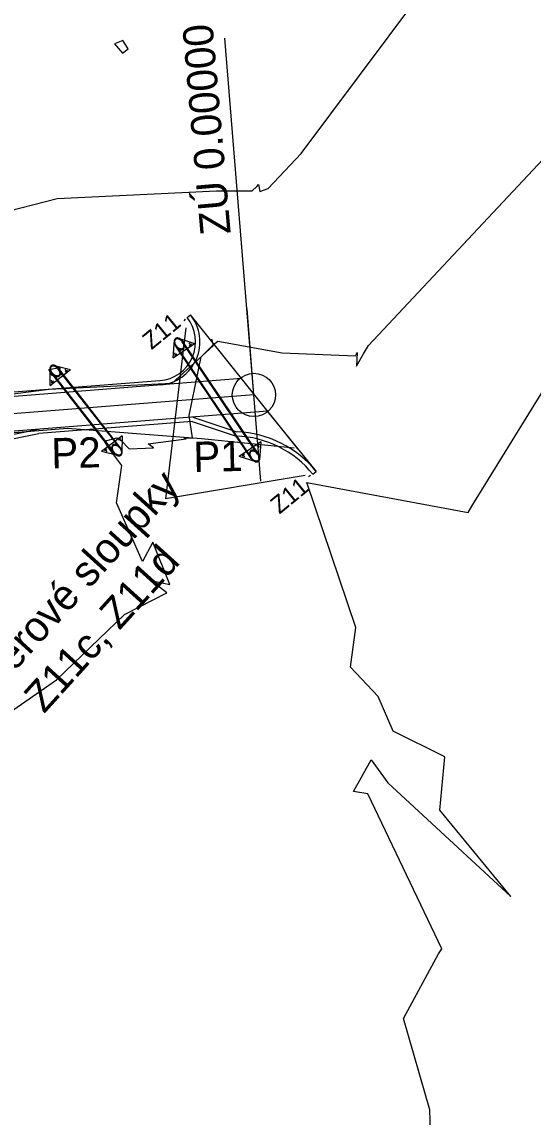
# Model space of a CAD drawing. Extents: x -549394 to -546608, y -1037055 to -1033629.
# Drawn here: x -547531.9 to -547472.7, y -1035190.9 to -1035064.3 of the extents above; entities that cross this region are included whole.
import ezdxf

# ---------------------------------------------------------------- set-up
doc = ezdxf.new("R2010")
doc.units = 0
for name, color, linetype in [('hlavni_vrst', 7, 'Continuous'), ('hrana_L', 7, 'Continuous'), ('norm_vrst', 7, 'Continuous'), ('POLYGONY_SITUACE_PO', 7, 'Continuous'), ('x_navrh_C1', 7, 'Continuous'), ('x_osa_C1', 7, 'Continuous'), ('x_popis_C1', 7, 'Continuous'), ('x_popis_oblouky_C1', 7, 'Continuous'), ('x_popis_pricne_rezy_C1', 7, 'Continuous'), ('x_propustek', 7, 'Continuous'), ('x_SDZ_C1', 7, 'Continuous')]:
    doc.layers.add(name, color=color, linetype=linetype)

msp = doc.modelspace()

# ---------------------------------------------------------------- linework, layer by layer
at = {"layer": 'hlavni_vrst'}
for p, q in [((-547479.83, -1035120.29), (-547467.32, -1035100.01)), ((-547498.94, -1035117.55), (-547498.94, -1035117.55)), ((-547498.94, -1035117.55), (-547498.94, -1035117.55)), ((-547498.94, -1035117.55), (-547498.94, -1035117.55)), ((-547498.94, -1035117.55), (-547480.25, -1035121.02)), ((-547498.94, -1035117.55), (-547498.94, -1035117.55)), ((-547493.26, -1035134.32), (-547498.94, -1035117.55)), ((-547498.94, -1035117.55), (-547498.94, -1035117.55)), ((-547498.94, -1035117.55), (-547498.94, -1035117.55)), ((-547498.94, -1035117.55), (-547498.94, -1035117.55)), ((-547480.25, -1035121.02), (-547479.83, -1035120.29)), ((-547493.87, -1035138.92), (-547493.26, -1035134.32)), ((-547490.66, -1035142.33), (-547493.87, -1035138.92)), ((-547488.93, -1035146.33), (-547490.66, -1035142.33)), ((-547482.97, -1035149.28), (-547488.93, -1035146.33)), ((-547493.51, -1035153.28), (-547491.47, -1035149.64)), ((-547491.47, -1035149.64), (-547489.56, -1035152.3)), ((-547483.54, -1035155.44), (-547482.97, -1035149.28)), ((-547489.56, -1035152.3), (-547475.31, -1035165.43)), ((-547491.88, -1035153.58), (-547493.51, -1035153.28)), ((-547483.29, -1035171.5), (-547491.88, -1035153.58)), ((-547475.31, -1035165.43), (-547483.54, -1035155.44)), ((-547483.7, -1035172.06), (-547483.29, -1035171.5)), ((-547487.72, -1035179.56), (-547483.7, -1035172.06)), ((-547484.7, -1035190.12), (-547487.72, -1035179.56)), ((-547483.99, -1035210.2), (-547484.7, -1035190.12))]:
    msp.add_line(p, q, dxfattribs=at)
at = {"layer": 'hrana_L'}
for p, q in [((-547509.73, -1035101.72), (-547514.54, -1035106.1)), ((-547509.73, -1035101.72), (-547509.94, -1035101)), ((-547528.76, -1035106.82), (-547550.14, -1035109.56)), ((-547514.54, -1035106.1), (-547528.76, -1035106.82)), ((-547540.44, -1035112.37), (-547526.63, -1035111.28)), ((-547526.63, -1035111.28), (-547511.12, -1035112.47)), ((-547511.12, -1035112.47), (-547500.41, -1035113.54))]:
    msp.add_line(p, q, dxfattribs=at)
at = {"layer": 'norm_vrst'}
for p, q in [((-547499.6, -1035079.52), (-547480.94, -1035054.58)), ((-547520.21, -1035066.44), (-547521.2, -1035066.83)), ((-547519.62, -1035067.42), (-547520.21, -1035066.44)), ((-547521.2, -1035066.83), (-547520.26, -1035067.93)), ((-547520.26, -1035067.93), (-547519.62, -1035067.42)), ((-547491.77, -1035101.71), (-547459.89, -1035067.67)), ((-547503.4, -1035083.58), (-547499.6, -1035079.52)), ((-547527.84, -1035084.74), (-547509.37, -1035083.84)), ((-547509.37, -1035083.84), (-547505.24, -1035083.85)), ((-547505.24, -1035083.85), (-547504.71, -1035083.33)), ((-547504.71, -1035083.33), (-547504.53, -1035083.09)), ((-547504.53, -1035083.09), (-547504.35, -1035083.91)), ((-547504.35, -1035083.91), (-547503.4, -1035083.58)), ((-547535.88, -1035086.78), (-547527.84, -1035084.74)), ((-547511.17, -1035103.03), (-547509.75, -1035101.64)), ((-547509.75, -1035101.64), (-547509.24, -1035101.21)), ((-547509.24, -1035101.21), (-547501.78, -1035102.57)), ((-547492.36, -1035102.68), (-547491.77, -1035101.71)), ((-547512.55, -1035109.82), (-547511.17, -1035103.03)), ((-547501.78, -1035102.57), (-547493.31, -1035102.92)), ((-547493.31, -1035102.92), (-547493.12, -1035102.53)), ((-547493.12, -1035102.53), (-547493.18, -1035104.1)), ((-547493.18, -1035104.1), (-547492.36, -1035102.68)), ((-547528.79, -1035104.51), (-547527.52, -1035104.28)), ((-547527.52, -1035104.28), (-547527.55, -1035104.73)), ((-547528.43, -1035105.18), (-547528.79, -1035104.51)), ((-547528, -1035105.18), (-547528.43, -1035105.18)), ((-547527.97, -1035105.44), (-547528, -1035105.18)), ((-547527.34, -1035105.07), (-547527.97, -1035105.44)), ((-547527.55, -1035104.73), (-547527.34, -1035105.07)), ((-547512.17, -1035112.39), (-547512.55, -1035109.82)), ((-547522.36, -1035112.78), (-547520.92, -1035112.39)), ((-547521.86, -1035113.6), (-547522.36, -1035112.78)), ((-547520.92, -1035112.39), (-547520.45, -1035112.67)), ((-547520.45, -1035112.67), (-547519.48, -1035113.67)), ((-547517.3, -1035113.1), (-547512.88, -1035112.5)), ((-547516.67, -1035113.57), (-547517.3, -1035113.1)), ((-547513.13, -1035112.4), (-547512.17, -1035112.39)), ((-547512.88, -1035112.5), (-547513.13, -1035112.4)), ((-547520.33, -1035115.59), (-547521.86, -1035113.6)), ((-547519.48, -1035113.67), (-547516.67, -1035113.57)), ((-547520.94, -1035119.91), (-547520.33, -1035115.59)), ((-547517.94, -1035126.69), (-547520.94, -1035119.91)), ((-547516.76, -1035124.47), (-547517.94, -1035126.69)), ((-547514.77, -1035129.37), (-547516.76, -1035124.47)), ((-547515.15, -1035130.32), (-547516.97, -1035128.88)), ((-547516.97, -1035128.88), (-547514.77, -1035129.37)), ((-547520.05, -1035132.83), (-547515.15, -1035130.32)), ((-547527.89, -1035140.38), (-547520.05, -1035132.83)), ((-547540.33, -1035148.97), (-547527.89, -1035140.38))]:
    msp.add_line(p, q, dxfattribs=at)
at = {"layer": 'POLYGONY_SITUACE_PO'}
msp.add_circle((-547505.05, -1035107.44), 2.5, dxfattribs=at)
at = {"layer": 'x_navrh_C1'}
for p, q in [((-547512.79, -1035098.49), (-547512.4, -1035098.17)), ((-547499.96, -1035113.69), (-547512.4, -1035098.17)), ((-547506.49, -1035105.54), (-547540.28, -1035108.21)), ((-547503.46, -1035109.32), (-547539.97, -1035112.19)), ((-547503.51, -1035109.32), (-547497.84, -1035116.3)), ((-547512.19, -1035110.51), (-547529.93, -1035111.9)), ((-547512.19, -1035110.51), (-547507.1, -1035112.19)), ((-547512.13, -1035110), (-547507.01, -1035111.69)), ((-547539.87, -1035113.39), (-547530, -1035111.41)), ((-547539.81, -1035113.89), (-547529.93, -1035111.9)), ((-547498.22, -1035116.61), (-547497.84, -1035116.3))]:
    msp.add_line(p, q, dxfattribs=at)
msp.add_lwpolyline([(-547515.94, -1035105.79), (-547540.32, -1035107.71)], dxfattribs=at)
for centre, radius, start, end in [((-547516.3, -1035101.3), 4.5, 274.5085, 38.7215), ((-547516.3, -1035101.3), 5, 274.5085, 38.7215), ((-547507.53, -1035124.18), 12.5, 39.1118, 87.5903), ((-547507.53, -1035124.18), 12, 39.1118, 87.9203)]:
    msp.add_arc(centre, radius, start, end, dxfattribs=at)
at = {"layer": 'x_osa_C1'}
msp.add_lwpolyline([(-547505.05, -1035107.44), (-547549.17, -1035110.91)], dxfattribs=at)
at = {"layer": 'x_popis_oblouky_C1'}
msp.add_lwpolyline([(-547505.05, -1035107.44), (-547508.42, -1035066.2)], dxfattribs=at)
at = {"layer": 'x_popis_pricne_rezy_C1'}
msp.add_lwpolyline([(-547504.26, -1035117.4), (-547505.05, -1035107.44), (-547505.84, -1035097.47)], dxfattribs=at)
at = {"layer": 'x_propustek'}
for p, q in [((-547514.41, -1035103.15), (-547514.25, -1035101.09)), ((-547514.41, -1035103.15), (-547511.92, -1035101.48)), ((-547513.89, -1035100.85), (-547514.25, -1035101.09)), ((-547505.38, -1035114.77), (-547514.1, -1035101.8)), ((-547505.32, -1035114.73), (-547514.03, -1035101.76)), ((-547513.89, -1035100.85), (-547511.92, -1035101.48)), ((-547504.63, -1035114.27), (-547513.35, -1035101.3)), ((-547504.57, -1035114.22), (-547513.29, -1035101.26)), ((-547512.31, -1035101.74), (-547512.53, -1035101.41)), ((-547512.39, -1035101.8), (-547512.5, -1035101.63)), ((-547512.23, -1035101.69), (-547512.34, -1035101.52)), ((-547514.02, -1035102.89), (-547514.24, -1035102.56)), ((-547514.1, -1035102.94), (-547514.21, -1035102.78)), ((-547513.93, -1035102.83), (-547514.04, -1035102.67)), ((-547528.65, -1035106.33), (-547528.64, -1035104.26)), ((-547528.65, -1035106.33), (-547526.29, -1035104.49)), ((-547528.3, -1035104), (-547528.64, -1035104.26)), ((-547528.3, -1035104), (-547526.29, -1035104.49)), ((-547520.59, -1035113.56), (-547527.73, -1035104.41)), ((-547520.53, -1035113.52), (-547527.67, -1035104.36)), ((-547526.66, -1035104.78), (-547526.91, -1035104.46)), ((-547528.28, -1035106.04), (-547528.53, -1035105.72)), ((-547521.3, -1035114.12), (-547528.44, -1035104.96)), ((-547521.24, -1035114.07), (-547528.38, -1035104.91)), ((-547526.74, -1035104.84), (-547526.86, -1035104.68)), ((-547526.58, -1035104.71), (-547526.7, -1035104.56)), ((-547528.36, -1035106.1), (-547528.48, -1035105.94)), ((-547528.2, -1035105.98), (-547528.33, -1035105.82)), ((-547520.31, -1035112.15), (-547522.68, -1035113.99)), ((-547520.76, -1035112.5), (-547520.64, -1035112.66)), ((-547520.68, -1035112.44), (-547520.44, -1035112.75)), ((-547520.61, -1035112.38), (-547520.48, -1035112.53)), ((-547520.31, -1035112.15), (-547520.33, -1035114.22)), ((-547504.26, -1035112.87), (-547506.75, -1035114.55)), ((-547504.74, -1035113.19), (-547504.63, -1035113.36)), ((-547504.65, -1035113.14), (-547504.43, -1035113.47)), ((-547504.57, -1035113.08), (-547504.46, -1035113.25)), ((-547504.26, -1035112.87), (-547504.42, -1035114.94)), ((-547520.66, -1035114.48), (-547522.68, -1035113.99)), ((-547522.38, -1035113.76), (-547522.26, -1035113.92)), ((-547522.31, -1035113.7), (-547522.06, -1035114.02)), ((-547522.23, -1035113.64), (-547522.1, -1035113.8)), ((-547520.66, -1035114.48), (-547520.33, -1035114.22)), ((-547504.78, -1035115.18), (-547506.75, -1035114.55)), ((-547506.44, -1035114.34), (-547506.33, -1035114.51)), ((-547506.36, -1035114.28), (-547506.14, -1035114.62)), ((-547506.28, -1035114.23), (-547506.17, -1035114.39)), ((-547504.78, -1035115.18), (-547504.42, -1035114.94))]:
    msp.add_line(p, q, dxfattribs=at)
for points in [[(-547514.11, -1035100.91), (-547514.12, -1035100.91), (-547514.14, -1035100.92), (-547514.16, -1035100.95), (-547514.17, -1035100.96), (-547514.2, -1035100.99), (-547514.22, -1035101.02), (-547514.26, -1035101.12), (-547514.28, -1035101.19), (-547514.27, -1035101.36), (-547514.26, -1035101.45), (-547514.2, -1035101.63), (-547514.15, -1035101.72), (-547514.04, -1035101.89), (-547513.97, -1035101.96), (-547513.83, -1035102.08), (-547513.75, -1035102.13), (-547513.6, -1035102.2), (-547513.52, -1035102.21), (-547513.44, -1035102.21), (-547513.42, -1035102.21), (-547513.39, -1035102.2), (-547513.37, -1035102.2), (-547513.33, -1035102.18), (-547513.3, -1035102.17), (-547513.27, -1035102.15)], [(-547514.07, -1035100.97), (-547514.09, -1035100.98), (-547514.11, -1035101), (-547514.14, -1035101.04), (-547514.15, -1035101.06), (-547514.18, -1035101.11), (-547514.18, -1035101.14), (-547514.2, -1035101.2), (-547514.2, -1035101.24), (-547514.2, -1035101.31), (-547514.2, -1035101.35), (-547514.18, -1035101.43), (-547514.17, -1035101.47), (-547514.13, -1035101.6), (-547514.09, -1035101.68), (-547513.98, -1035101.84), (-547513.92, -1035101.91), (-547513.82, -1035101.99), (-547513.79, -1035102.02), (-547513.72, -1035102.06), (-547513.68, -1035102.08), (-547513.61, -1035102.11), (-547513.58, -1035102.12), (-547513.52, -1035102.13), (-547513.49, -1035102.14), (-547513.43, -1035102.13), (-547513.4, -1035102.13), (-547513.36, -1035102.12), (-547513.33, -1035102.1), (-547513.29, -1035102.08), (-547513.28, -1035102.06), (-547513.24, -1035102.02), (-547513.23, -1035102), (-547513.21, -1035101.95), (-547513.2, -1035101.92), (-547513.19, -1035101.86), (-547513.18, -1035101.82), (-547513.18, -1035101.75), (-547513.19, -1035101.71), (-547513.2, -1035101.63), (-547513.21, -1035101.58), (-547513.25, -1035101.46), (-547513.3, -1035101.38), (-547513.4, -1035101.22), (-547513.46, -1035101.15), (-547513.56, -1035101.07), (-547513.6, -1035101.04), (-547513.67, -1035101), (-547513.7, -1035100.98), (-547513.77, -1035100.95), (-547513.8, -1035100.94), (-547513.87, -1035100.93), (-547513.9, -1035100.92), (-547513.95, -1035100.92), (-547513.98, -1035100.93), (-547514.03, -1035100.94), (-547514.05, -1035100.95), (-547514.07, -1035100.97)], [(-547513.27, -1035102.15), (-547513.26, -1035102.14), (-547513.25, -1035102.14), (-547513.22, -1035102.11), (-547513.21, -1035102.1), (-547513.18, -1035102.07), (-547513.16, -1035102.04), (-547513.12, -1035101.94), (-547513.11, -1035101.87), (-547513.11, -1035101.7), (-547513.13, -1035101.61), (-547513.19, -1035101.43), (-547513.23, -1035101.34), (-547513.34, -1035101.17), (-547513.41, -1035101.1), (-547513.55, -1035100.98), (-547513.63, -1035100.93), (-547513.78, -1035100.86), (-547513.86, -1035100.85), (-547513.95, -1035100.85), (-547513.96, -1035100.85), (-547513.99, -1035100.86), (-547514.01, -1035100.86), (-547514.06, -1035100.87), (-547514.09, -1035100.89), (-547514.11, -1035100.91)], [(-547528.52, -1035104.07), (-547528.53, -1035104.08), (-547528.54, -1035104.09), (-547528.56, -1035104.11), (-547528.57, -1035104.12), (-547528.6, -1035104.16), (-547528.62, -1035104.19), (-547528.65, -1035104.29), (-547528.66, -1035104.36), (-547528.65, -1035104.53), (-547528.63, -1035104.62), (-547528.55, -1035104.8), (-547528.5, -1035104.88), (-547528.38, -1035105.04), (-547528.31, -1035105.11), (-547528.16, -1035105.22), (-547528.08, -1035105.27), (-547527.92, -1035105.32), (-547527.84, -1035105.33), (-547527.75, -1035105.32), (-547527.74, -1035105.32), (-547527.7, -1035105.31), (-547527.69, -1035105.31), (-547527.64, -1035105.29), (-547527.62, -1035105.27), (-547527.59, -1035105.25)], [(-547528.47, -1035104.13), (-547528.49, -1035104.14), (-547528.51, -1035104.16), (-547528.54, -1035104.2), (-547528.55, -1035104.22), (-547528.57, -1035104.28), (-547528.57, -1035104.31), (-547528.58, -1035104.37), (-547528.58, -1035104.41), (-547528.58, -1035104.48), (-547528.57, -1035104.52), (-547528.55, -1035104.6), (-547528.54, -1035104.64), (-547528.49, -1035104.76), (-547528.44, -1035104.84), (-547528.32, -1035104.99), (-547528.26, -1035105.05), (-547528.15, -1035105.13), (-547528.12, -1035105.16), (-547528.04, -1035105.19), (-547528.01, -1035105.21), (-547527.94, -1035105.23), (-547527.9, -1035105.24), (-547527.84, -1035105.25), (-547527.81, -1035105.25), (-547527.75, -1035105.24), (-547527.72, -1035105.24), (-547527.68, -1035105.22), (-547527.66, -1035105.21), (-547527.62, -1035105.18), (-547527.6, -1035105.16), (-547527.57, -1035105.12), (-547527.56, -1035105.1), (-547527.54, -1035105.04), (-547527.54, -1035105.02), (-547527.53, -1035104.95), (-547527.53, -1035104.92), (-547527.53, -1035104.84), (-547527.54, -1035104.8), (-547527.56, -1035104.72), (-547527.57, -1035104.68), (-547527.62, -1035104.56), (-547527.67, -1035104.48), (-547527.79, -1035104.33), (-547527.85, -1035104.27), (-547527.96, -1035104.19), (-547527.99, -1035104.17), (-547528.07, -1035104.13), (-547528.1, -1035104.11), (-547528.17, -1035104.09), (-547528.21, -1035104.08), (-547528.27, -1035104.07), (-547528.3, -1035104.07), (-547528.36, -1035104.08), (-547528.38, -1035104.08), (-547528.43, -1035104.1), (-547528.45, -1035104.11), (-547528.47, -1035104.13)], [(-547527.59, -1035105.25), (-547527.58, -1035105.24), (-547527.57, -1035105.23), (-547527.55, -1035105.21), (-547527.54, -1035105.2), (-547527.51, -1035105.16), (-547527.49, -1035105.13), (-547527.46, -1035105.03), (-547527.45, -1035104.96), (-547527.46, -1035104.79), (-547527.48, -1035104.7), (-547527.56, -1035104.53), (-547527.61, -1035104.44), (-547527.73, -1035104.28), (-547527.8, -1035104.21), (-547527.95, -1035104.1), (-547528.03, -1035104.05), (-547528.19, -1035104), (-547528.27, -1035103.99), (-547528.36, -1035104), (-547528.37, -1035104), (-547528.4, -1035104.01), (-547528.42, -1035104.02), (-547528.47, -1035104.03), (-547528.49, -1035104.05), (-547528.52, -1035104.07)], [(-547521.37, -1035113.22), (-547521.39, -1035113.23), (-547521.4, -1035113.24), (-547521.42, -1035113.27), (-547521.43, -1035113.28), (-547521.46, -1035113.32), (-547521.47, -1035113.35), (-547521.51, -1035113.44), (-547521.52, -1035113.52), (-547521.5, -1035113.69), (-547521.48, -1035113.78), (-547521.41, -1035113.95), (-547521.36, -1035114.04), (-547521.23, -1035114.2), (-547521.16, -1035114.27), (-547521.01, -1035114.38), (-547520.93, -1035114.42), (-547520.77, -1035114.48), (-547520.7, -1035114.49), (-547520.61, -1035114.48), (-547520.59, -1035114.47), (-547520.56, -1035114.47), (-547520.55, -1035114.46), (-547520.5, -1035114.44), (-547520.47, -1035114.43), (-547520.45, -1035114.41)], [(-547520.5, -1035114.35), (-547520.48, -1035114.34), (-547520.46, -1035114.32), (-547520.43, -1035114.28), (-547520.42, -1035114.25), (-547520.4, -1035114.2), (-547520.39, -1035114.17), (-547520.38, -1035114.11), (-547520.38, -1035114.07), (-547520.39, -1035114), (-547520.4, -1035113.96), (-547520.42, -1035113.88), (-547520.43, -1035113.84), (-547520.48, -1035113.72), (-547520.53, -1035113.64), (-547520.64, -1035113.49), (-547520.71, -1035113.42), (-547520.82, -1035113.34), (-547520.85, -1035113.32), (-547520.92, -1035113.28), (-547520.96, -1035113.27), (-547521.03, -1035113.24), (-547521.07, -1035113.24), (-547521.13, -1035113.23), (-547521.16, -1035113.23), (-547521.22, -1035113.23), (-547521.24, -1035113.24), (-547521.29, -1035113.26), (-547521.31, -1035113.27), (-547521.35, -1035113.3), (-547521.36, -1035113.32), (-547521.39, -1035113.36), (-547521.4, -1035113.38), (-547521.42, -1035113.43), (-547521.43, -1035113.46), (-547521.44, -1035113.53), (-547521.44, -1035113.56), (-547521.43, -1035113.64), (-547521.43, -1035113.68), (-547521.41, -1035113.75), (-547521.39, -1035113.8), (-547521.34, -1035113.92), (-547521.3, -1035114), (-547521.18, -1035114.15), (-547521.11, -1035114.21), (-547521.01, -1035114.29), (-547520.97, -1035114.31), (-547520.9, -1035114.35), (-547520.86, -1035114.37), (-547520.79, -1035114.39), (-547520.76, -1035114.4), (-547520.69, -1035114.41), (-547520.66, -1035114.41), (-547520.61, -1035114.4), (-547520.58, -1035114.39), (-547520.53, -1035114.38), (-547520.51, -1035114.37), (-547520.5, -1035114.35)], [(-547520.45, -1035114.41), (-547520.44, -1035114.4), (-547520.42, -1035114.39), (-547520.4, -1035114.37), (-547520.39, -1035114.35), (-547520.37, -1035114.31), (-547520.35, -1035114.29), (-547520.32, -1035114.19), (-547520.31, -1035114.11), (-547520.32, -1035113.94), (-547520.34, -1035113.86), (-547520.41, -1035113.68), (-547520.46, -1035113.6), (-547520.59, -1035113.44), (-547520.66, -1035113.37), (-547520.81, -1035113.25), (-547520.89, -1035113.21), (-547521.05, -1035113.16), (-547521.13, -1035113.15), (-547521.21, -1035113.16), (-547521.23, -1035113.16), (-547521.26, -1035113.17), (-547521.28, -1035113.17), (-547521.32, -1035113.19), (-547521.35, -1035113.2), (-547521.37, -1035113.22)], [(-547505.4, -1035113.87), (-547505.41, -1035113.88), (-547505.42, -1035113.89), (-547505.45, -1035113.91), (-547505.46, -1035113.92), (-547505.49, -1035113.96), (-547505.5, -1035113.99), (-547505.55, -1035114.08), (-547505.56, -1035114.16), (-547505.56, -1035114.33), (-547505.54, -1035114.42), (-547505.48, -1035114.6), (-547505.44, -1035114.69), (-547505.33, -1035114.85), (-547505.26, -1035114.93), (-547505.12, -1035115.05), (-547505.04, -1035115.1), (-547504.88, -1035115.17), (-547504.81, -1035115.18), (-547504.72, -1035115.18), (-547504.71, -1035115.18), (-547504.67, -1035115.17), (-547504.66, -1035115.17), (-547504.61, -1035115.15), (-547504.58, -1035115.14), (-547504.56, -1035115.12)], [(-547504.6, -1035115.06), (-547504.58, -1035115.05), (-547504.56, -1035115.03), (-547504.53, -1035114.99), (-547504.52, -1035114.97), (-547504.49, -1035114.92), (-547504.48, -1035114.89), (-547504.47, -1035114.82), (-547504.47, -1035114.79), (-547504.47, -1035114.71), (-547504.47, -1035114.67), (-547504.49, -1035114.59), (-547504.5, -1035114.55), (-547504.54, -1035114.43), (-547504.58, -1035114.34), (-547504.69, -1035114.19), (-547504.75, -1035114.12), (-547504.85, -1035114.03), (-547504.88, -1035114.01), (-547504.95, -1035113.96), (-547504.99, -1035113.95), (-547505.06, -1035113.92), (-547505.09, -1035113.91), (-547505.15, -1035113.89), (-547505.18, -1035113.89), (-547505.24, -1035113.89), (-547505.27, -1035113.9), (-547505.31, -1035113.91), (-547505.34, -1035113.92), (-547505.38, -1035113.95), (-547505.39, -1035113.96), (-547505.42, -1035114), (-547505.44, -1035114.03), (-547505.46, -1035114.08), (-547505.47, -1035114.11), (-547505.48, -1035114.17), (-547505.49, -1035114.21), (-547505.49, -1035114.28), (-547505.48, -1035114.32), (-547505.47, -1035114.4), (-547505.46, -1035114.44), (-547505.41, -1035114.57), (-547505.37, -1035114.65), (-547505.27, -1035114.81), (-547505.21, -1035114.88), (-547505.11, -1035114.96), (-547505.07, -1035114.99), (-547505, -1035115.03), (-547504.97, -1035115.05), (-547504.9, -1035115.08), (-547504.87, -1035115.09), (-547504.8, -1035115.1), (-547504.77, -1035115.1), (-547504.72, -1035115.1), (-547504.69, -1035115.1), (-547504.64, -1035115.08), (-547504.62, -1035115.07), (-547504.6, -1035115.06)], [(-547504.56, -1035115.12), (-547504.54, -1035115.11), (-547504.53, -1035115.1), (-547504.51, -1035115.08), (-547504.5, -1035115.07), (-547504.47, -1035115.03), (-547504.45, -1035115), (-547504.41, -1035114.91), (-547504.39, -1035114.84), (-547504.4, -1035114.67), (-547504.41, -1035114.58), (-547504.47, -1035114.4), (-547504.52, -1035114.31), (-547504.63, -1035114.14), (-547504.69, -1035114.07), (-547504.84, -1035113.94), (-547504.91, -1035113.89), (-547505.07, -1035113.83), (-547505.15, -1035113.81), (-547505.23, -1035113.82), (-547505.25, -1035113.82), (-547505.28, -1035113.82), (-547505.3, -1035113.83), (-547505.34, -1035113.84), (-547505.37, -1035113.86), (-547505.4, -1035113.87)]]:
    msp.add_open_spline(points, degree=3, dxfattribs=at)
at = {"layer": 'x_SDZ_C1'}
for p, q in [((-547513, -1035098.68), (-547513.18, -1035098.85)), ((-547498.51, -1035116.77), (-547498.72, -1035116.91))]:
    msp.add_line(p, q, dxfattribs=at)
for points in [[(-547512.95, -1035099.68), (-547515.28, -1035119.46)], [(-547499.12, -1035116.74), (-547515.28, -1035119.46)]]:
    msp.add_lwpolyline(points, dxfattribs=at)

# ---------------------------------------------------------------- texts
at = {"layer": 'x_popis_C1'}
for s, p in [('P2', (-547528.47, -1035115.93)), ('P1', (-547512.03, -1035116.35))]:
    msp.add_text(s, height=3.5, rotation=1.225, dxfattribs=at).set_placement(p)
at = {"layer": 'x_popis_oblouky_C1'}
msp.add_text('ZÚ 0.00000', height=3.5, rotation=94.9843, dxfattribs=at).set_placement((-547507.73, -1035088.78))
at = {"layer": 'x_SDZ_C1'}
for s, height, rotation, p in [('Z11', 2, 39.2045, (-547516.91, -1035102.28)), ('Směrové sloupky', 3.5, 47.8559, (-547537.54, -1035144.75)), ('Z11', 2, 39.2045, (-547502.1, -1035121.29)), ('Z11c, Z11d', 3.5, 47.8559, (-547529.34, -1035144.37))]:
    msp.add_text(s, height=height, rotation=rotation, dxfattribs=at).set_placement(p)

doc.saveas('drawing.dxf')
